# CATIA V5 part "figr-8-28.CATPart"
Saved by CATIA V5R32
Part number: Part1
Bounding box of the stored display mesh (mm): x 37.5 to 207.5, y 10 to 85, z 0 to 113
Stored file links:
  D:\PROJECTS\Project 2022\CATIA V5 6R 2022\Resources\Part Files\c08_catia_v5_6r2022_prt\figr-8-28.CATPart
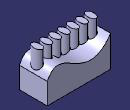
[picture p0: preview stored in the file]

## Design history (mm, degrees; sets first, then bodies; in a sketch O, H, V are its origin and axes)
Set1
  Plane1: type Offset, RefPlane xy-plane, Offset 113
Body1 (main body)
  Sketch1 on xy-plane, origin (0, 0, 0), H (1, 0, 0), V (0, 1, 0)
    line L1 (-37.5, 85) -> (37.5, 85)
    line L2 (37.5, 85) -> (37.5, -85)
    line L3 (37.5, -85) -> (-37.5, -85)
    line L4 (-37.5, -85) -> (-37.5, 85)
    axis line L5 (37.5, -85) -> (-37.5, 85)
    length L3 = 75
    length L2 = 170
    horizontal: L1 H, L3 H
    vertical: L2 V, L4 V
    midpoint: O L5
  Pad1: profile Sketch1, direction (0, 0, 1), length 83
  Sketch2 on face of Pad1, origin (37.5, 0, 0), H (0, 1, 0), V (0, 0, 1)
    spline S1 through (-85, 56.7422) (-58.5369, 80.0687) (-27.7952, 70.201) (85, 83)
    reference projected line E1 (85, 0) -> (85, 83) from edge [face of Pad1 | face of Pad1]
    reference projected line E2 (-85, 0) -> (-85, 83) from edge [face of Pad1 | face of Pad1]
    reference projected line E3 (-85, 83) -> (85, 83) from edge [face of Pad1 | face of Pad1]
    point P1 (85, 83)
    point P3 (-85, 56.7422)
    coincidence: P1 E1, P3 E2, P1 E3
  Pocket1: profile Sketch2, direction (-1, 0, 0), length 83
  Rotate1: Axis edge [face of Pad1 | face of Pad1], ToTransfor Pocket1, Angle 90
  Sketch3 on Plane1, origin (0, 0, 113), H (1, 0, 0), V (0, 1, 0)
    ellipse A1 centre (195.4286, 45.9861) semi-axes 14.9247, 8.8005 rotation 90
  Pad2: profile Sketch3, direction (0, 0, -1), up to face of Pocket1
  RectPattern1: of Pad2, direction 1 instances 7, spacing 24, along edge [face of Pad1 | face of Pad1]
